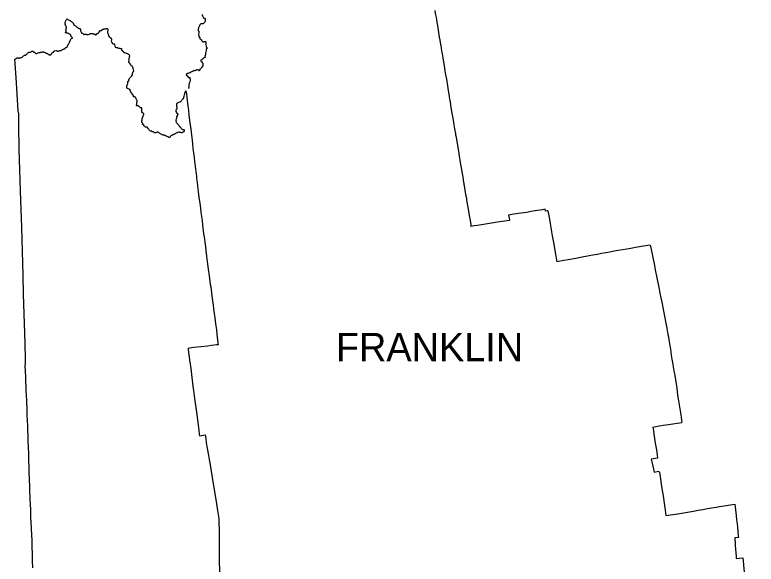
# Model space of a CAD drawing. Extents: x 1104458 to 2179854, y 15641624 to 17244911.
# Drawn here: x 1104458 to 1380839, y 16278003 to 16482866 of the extents above; entities that cross this region are included whole.
import ezdxf

# ---------------------------------------------------------------- set-up
doc = ezdxf.new("R2010")
doc.units = 0
doc.layers.add('ANNOTATION', color=7, linetype='Continuous')
doc.layers.add('CO BORDER', color=7, linetype='Continuous')

msp = doc.modelspace()

# ---------------------------------------------------------------- linework, layer by layer
at = {"layer": 'CO BORDER'}
for points in [[(1261052, 16484417), (1261224, 16483380), (1261498, 16481910), (1261631, 16481149), (1261802, 16480030), (1261997, 16478885), (1262714, 16474568), (1262900, 16473357), (1263165, 16471854), (1263235, 16471402), (1263424, 16470391)], [(1105767, 16446280), (1105725, 16447090), (1104983, 16459446), (1104458, 16466379), (1104525, 16466379), (1104625, 16466346), (1104708, 16466398), (1104775, 16466454), (1104833, 16466530), (1104983, 16466631), (1105258, 16466779), (1105457, 16466854), (1105658, 16466812), (1105791, 16466723), (1105933, 16466664), (1106049, 16466648), (1106149, 16466697), (1106257, 16466789), (1106308, 16466805), (1106416, 16466822), (1106658, 16466904), (1106958, 16466995), (1107132, 16467130), (1107616, 16467471), (1107732, 16467573), (1107907, 16467753), (1108016, 16467812), (1108116, 16467789), (1108324, 16467812), (1108507, 16467871), (1108599, 16467921), (1108782, 16468121), (1108916, 16468331), (1109057, 16468429), (1109174, 16468472), (1109232, 16468597), (1109316, 16468738), (1109507, 16468862), (1109682, 16468915), (1109899, 16468948), (1110240, 16468889), (1110357, 16468905), (1110591, 16469079), (1110690, 16469164), (1110849, 16469279), (1111032, 16469295), (1111132, 16469295), (1111282, 16469230), (1111374, 16469164), (1111457, 16469030), (1111582, 16468997), (1111741, 16468931), (1111907, 16468780), (1112132, 16468531), (1112307, 16468455), (1112440, 16468406), (1112565, 16468413), (1112715, 16468429), (1112932, 16468515), (1113174, 16468639), (1113498, 16468764), (1113915, 16468807), (1114174, 16468931), (1114548, 16468931), (1114690, 16469013), (1114965, 16469003), (1115157, 16468931), (1115415, 16468931), (1115540, 16468915), (1115707, 16468823), (1115757, 16468754), (1115882, 16468646), (1116056, 16468597), (1116298, 16468554), (1116448, 16468537), (1116557, 16468462), (1116707, 16468331), (1116790, 16468163), (1116957, 16468062), (1117132, 16468022), (1117248, 16468013), (1117390, 16467953), (1117440, 16467873), (1117748, 16467922), (1117915, 16467965), (1118007, 16468047), (1118123, 16468241), (1118190, 16468431), (1118257, 16468533), (1118431, 16468697), (1118565, 16468756), (1118706, 16468831), (1119015, 16469172), (1119231, 16469382), (1119373, 16469481), (1119840, 16469566), (1119981, 16469530), (1120273, 16469356), (1120423, 16469281), (1120631, 16469290), (1120748, 16469340), (1120981, 16469497), (1121114, 16469550), (1121415, 16469573), (1121564, 16469550), (1121748, 16469582), (1121914, 16469691), (1122123, 16469858), (1122189, 16469940), (1122489, 16470075), (1122681, 16470130), (1122789, 16470098), (1122881, 16470114), (1123123, 16470340), (1123348, 16470573), (1123506, 16470655), (1123698, 16470741), (1123881, 16470849), (1124047, 16470908), (1124156, 16470997), (1124131, 16471115), (1124147, 16471239), (1124147, 16471341), (1124181, 16471456), (1124306, 16471689), (1124464, 16472014), (1124564, 16472191), (1124681, 16472338), (1124781, 16472555), (1124864, 16472699), (1125131, 16473339), (1125347, 16473831), (1125447, 16473949), (1125630, 16474064), (1125889, 16474149), (1125930, 16474182), (1125939, 16474281), (1125930, 16474340), (1125764, 16474474), (1125672, 16474530), (1125589, 16474622), (1125522, 16474724), (1125447, 16474907), (1125389, 16475032), (1125297, 16475314), (1125222, 16475416), (1125147, 16475472), (1125047, 16475564), (1124880, 16475688), (1124664, 16475813), (1124456, 16475957), (1124181, 16476049), (1123814, 16476082), (1123681, 16476088), (1123531, 16476141), (1123431, 16476207), (1123397, 16476249), (1123389, 16476321), (1123406, 16476407), (1123472, 16476531), (1123589, 16476623), (1123605, 16476672), (1123622, 16476774), (1123572, 16477040), (1123547, 16477197), (1123531, 16477365), (1123505, 16477499), (1123564, 16477696), (1123622, 16477755), (1123681, 16477922), (1123689, 16478014), (1123664, 16478113), (1123664, 16478221), (1123681, 16478296), (1123647, 16478398), (1123597, 16478480), (1123547, 16478621), (1123489, 16478707), (1123389, 16478923), (1123272, 16479248), (1123289, 16479399), (1123289, 16479573), (1123256, 16479648), (1123247, 16479789), (1123230, 16479907), (1123230, 16479980), (1123272, 16480173), (1123339, 16480373), (1123464, 16480606), (1123564, 16480823), (1123780, 16481164), (1123814, 16481266), (1123897, 16481315), (1124105, 16481223), (1124272, 16481121), (1124430, 16480997), (1124522, 16480947), (1124672, 16480882), (1124922, 16480757), (1125072, 16480688), (1125197, 16480613), (1125347, 16480531), (1125497, 16480406), (1125605, 16480340), (1125980, 16479973), (1126089, 16479881), (1126147, 16479838), (1126255, 16479730), (1126289, 16479688), (1126322, 16479632), (1126314, 16479579), (1126347, 16479422), (1126405, 16479264), (1126447, 16479199), (1126488, 16479146), (1126630, 16479022), (1126680, 16478999)], [(1174314, 16483037), (1174349, 16482778), (1174395, 16482617), (1174456, 16482430), (1174585, 16482270), (1174830, 16481787), (1174960, 16481643), (1175092, 16481613), (1175250, 16481594), (1175349, 16481541), (1175430, 16481463), (1175461, 16481387), (1175475, 16481269), (1175383, 16480964), (1175397, 16480879), (1175360, 16480731), (1175364, 16480573), (1175360, 16480406), (1175271, 16480216), (1175158, 16480029), (1174902, 16479809), (1174748, 16479665), (1174604, 16479566), (1174370, 16479550), (1174144, 16479514), (1173952, 16479501), (1173817, 16479455), (1173647, 16479337), (1173577, 16479205), (1173406, 16479058), (1173337, 16478976), (1173273, 16478746), (1173193, 16478566), (1173010, 16478287), (1172939, 16478113), (1172877, 16477982), (1172769, 16477352), (1172795, 16477083), (1172866, 16476938), (1172963, 16476853), (1173027, 16476735), (1173046, 16476499), (1173021, 16476216), (1172959, 16475777), (1172954, 16475577), (1172996, 16475301), (1173058, 16475098), (1173070, 16474930), (1173097, 16474697), (1173143, 16474563), (1173259, 16474517), (1173382, 16474481), (1173456, 16474412), (1173487, 16474336), (1173499, 16474169), (1173461, 16473995), (1173450, 16473897), (1173583, 16473867), (1173878, 16473707), (1173990, 16473523), (1174044, 16473362), (1174172, 16473182), (1174267, 16472988), (1174398, 16472903), (1174580, 16472847), (1174880, 16472853), (1175064, 16472873), (1175331, 16472893), (1175474, 16472939), (1175581, 16472870), (1175611, 16472775), (1175669, 16472742), (1175692, 16472666), (1175648, 16472283), (1175608, 16472060), (1175595, 16471859), (1175624, 16471692), (1175801, 16471177), (1175812, 16470960), (1175909, 16470842), (1176127, 16470593), (1176123, 16470426), (1176068, 16470268), (1176033, 16470186), (1175950, 16470189), (1175899, 16470150), (1175836, 16470002), (1175795, 16469701), (1175625, 16468966), (1175602, 16468723), (1175587, 16468500), (1175554, 16468198), (1175568, 16468100), (1175548, 16467958), (1175477, 16467817), (1175434, 16467778), (1175379, 16467588), (1175342, 16467430), (1175369, 16467220), (1175391, 16467102), (1175389, 16467020), (1175328, 16466928), (1175161, 16466909), (1175035, 16466879), (1174731, 16466744), (1174628, 16466640), (1174575, 16466508), (1174538, 16466384), (1174478, 16466302), (1174351, 16466233), (1174232, 16466160), (1174140, 16466121), (1173918, 16465944), (1173815, 16465846), (1173739, 16465796), (1173761, 16465688), (1173956, 16465501), (1174013, 16465432), (1174344, 16465071), (1174433, 16464953), (1174495, 16464786), (1174509, 16464674), (1174539, 16464258), (1174542, 16464074), (1174511, 16463851), (1174449, 16463683), (1174403, 16463536), (1174384, 16463454), (1174315, 16463362), (1174180, 16463293), (1174052, 16463188), (1173991, 16463096), (1173972, 16462998), (1173562, 16462624), (1173402, 16462588), (1173382, 16462479), (1173361, 16462305), (1173358, 16462181), (1173339, 16462089), (1173287, 16462023), (1173227, 16461977), (1173135, 16461971), (1173013, 16462066), (1172950, 16462184), (1172860, 16462253), (1172786, 16462296), (1172703, 16462325), (1172654, 16462368), (1172538, 16462371), (1172328, 16462309), (1172176, 16462230), (1171990, 16462151), (1171713, 16462069), (1171645, 16462020), (1171552, 16461981), (1171461, 16462007), (1171404, 16462053), (1171312, 16462036), (1171230, 16462066), (1171113, 16462076), (1171020, 16462013), (1170934, 16461899), (1170823, 16461810), (1170636, 16461682), (1170460, 16461626), (1170334, 16461607), (1170099, 16461538), (1169938, 16461443), (1169894, 16461344), (1169808, 16461246), (1169640, 16461200), (1169303, 16461069), (1169110, 16461032), (1168992, 16460993), (1168859, 16460970), (1168502, 16460740), (1168434, 16460665), (1168391, 16460642), (1168355, 16460544), (1168620, 16460176), (1168798, 16459989), (1168944, 16459819), (1169228, 16459553), (1169411, 16459523), (1169561, 16459533), (1169669, 16459507), (1169758, 16459405), (1169752, 16459185), (1169801, 16458851), (1169819, 16458592), (1169798, 16458434), (1169708, 16457886), (1169645, 16457696), (1169566, 16457574), (1169469, 16457351), (1169430, 16457145), (1169373, 16456905), (1169332, 16456288), (1169291, 16456039), (1169284, 16455763), (1169247, 16455622), (1169234, 16455475), (1169208, 16455425)], [(1126680, 16478999), (1126858, 16478871), (1127016, 16478713), (1127205, 16478621), (1127302, 16478467), (1127432, 16478362), (1127526, 16478316), (1127703, 16478201), (1127851, 16478129), (1127960, 16478047), (1128012, 16477972), (1128096, 16477877), (1128260, 16477762), (1128372, 16477732), (1128720, 16477712), (1128815, 16477657), (1128910, 16477571), (1128954, 16477437), (1128973, 16477319), (1128973, 16477086), (1128981, 16476882), (1129070, 16476613), (1129171, 16476449), (1129259, 16476357), (1129351, 16476154), (1129497, 16476075), (1129791, 16475941), (1129936, 16475826), (1130031, 16475682), (1130059, 16475508), (1130158, 16475478), (1130273, 16475459), (1130390, 16475481), (1130568, 16475609), (1130802, 16475662), (1130894, 16475675), (1131010, 16475668), (1131206, 16475557), (1131405, 16475560), (1131612, 16475537), (1131887, 16475544), (1132138, 16475596), (1132248, 16475642), (1132350, 16475734), (1132443, 16475790), (1132553, 16475878), (1132621, 16475908), (1133128, 16475911), (1133294, 16475908), (1133443, 16475852), (1133548, 16475767), (1133764, 16475728), (1133914, 16475731), (1134072, 16475728), (1134188, 16475698), (1134348, 16475495), (1134430, 16475442), (1134578, 16475386), (1134754, 16475416), (1134841, 16475531), (1134918, 16475619), (1134956, 16475787), (1134990, 16475833), (1135041, 16475856), (1135125, 16475872), (1135232, 16475842), (1135366, 16475856), (1135468, 16475954), (1135536, 16476000), (1135648, 16476115), (1135760, 16476262), (1135830, 16476394), (1135967, 16476548), (1135994, 16476623), (1136212, 16476958), (1136431, 16477043), (1136530, 16477040), (1136597, 16477030), (1136689, 16477043), (1136962, 16477296), (1137080, 16477358), (1137174, 16477424), (1137292, 16477496), (1137375, 16477476), (1137593, 16477519), (1137745, 16477598), (1137956, 16477686), (1138305, 16477660), (1138476, 16477821), (1138609, 16477824), (1138792, 16477821), (1138883, 16477785), (1138988, 16477673), (1139060, 16477571), (1139100, 16477502), (1139131, 16477417), (1139155, 16477368), (1139162, 16477325), (1139161, 16477286), (1139174, 16477151), (1139090, 16476836), (1139052, 16476636), (1139040, 16476512), (1139020, 16476371), (1139032, 16476213), (1139093, 16476020), (1139173, 16475882), (1139226, 16475688), (1139289, 16475564), (1139369, 16475426), (1139423, 16475291), (1139454, 16475183), (1139419, 16475134), (1139400, 16475058), (1139374, 16474993), (1139463, 16474917), (1139578, 16474845), (1139657, 16474710), (1139671, 16474602), (1139738, 16474583), (1139950, 16474435), (1140073, 16474356), (1140131, 16474346), (1140188, 16474313), (1140263, 16474294), (1140367, 16474149), (1140430, 16474005), (1140462, 16473962), (1140501, 16473844), (1140512, 16473644), (1140519, 16473595), (1140516, 16473493), (1140506, 16473434), (1140513, 16473395), (1140435, 16473287), (1140450, 16473228), (1140448, 16473136), (1140436, 16473021), (1140482, 16472837), (1140538, 16472758), (1140576, 16472624), (1140623, 16472516), (1140679, 16472447), (1140710, 16472371), (1140759, 16472319), (1140882, 16472224), (1141153, 16472099), (1141352, 16472053), (1141442, 16472017), (1141509, 16471997), (1141582, 16471938), (1141635, 16471728), (1141738, 16471233), (1141839, 16470980), (1141854, 16470914), (1141911, 16470836), (1142025, 16470767), (1142199, 16470737), (1142290, 16470701), (1142697, 16470639), (1142919, 16470540), (1143126, 16470485), (1143300, 16470449), (1143624, 16470406), (1143831, 16470350), (1144022, 16470360), (1144172, 16470347), (1144221, 16470314), (1144260, 16470212), (1144279, 16469996), (1144368, 16469582), (1144457, 16469481), (1144563, 16469386), (1144719, 16469323), (1144859, 16469254), (1144938, 16469100), (1144984, 16468959), (1145072, 16468821), (1145387, 16468756), (1145676, 16468647), (1145907, 16468582), (1146048, 16468529), (1146486, 16468392), (1146657, 16468254), (1146804, 16468149), (1146952, 16468060), (1147065, 16467932), (1147179, 16467830), (1147261, 16467801), (1147301, 16467719), (1147245, 16467519), (1147182, 16467355), (1147078, 16467197), (1147038, 16466958), (1146935, 16466512), (1146916, 16466436), (1146880, 16466344), (1146902, 16466210), (1146974, 16466092), (1146991, 16465826), (1146953, 16465626), (1146845, 16465337), (1146874, 16465202), (1147069, 16464996), (1147431, 16464520), (1147552, 16464376), (1147615, 16464238), (1147914, 16463890), (1148053, 16463795), (1148167, 16463690), (1148271, 16463529), (1148355, 16463267), (1148392, 16463076), (1148446, 16462916), (1148514, 16462673), (1148526, 16462479), (1148581, 16462361), (1148649, 16462135), (1148689, 16462043), (1148677, 16461908), (1148623, 16461767), (1148544, 16461646), (1148424, 16461498), (1148336, 16461324), (1148290, 16461167), (1148252, 16460977), (1148215, 16460544), (1148220, 16460419), (1148209, 16460321), (1148166, 16460288), (1148090, 16460258), (1148024, 16460268), (1147981, 16460209), (1147927, 16460088), (1147897, 16459904), (1147854, 16459828), (1147565, 16459612), (1147486, 16459481), (1147305, 16459271), (1147175, 16459074), (1147096, 16458933), (1146943, 16458811), (1146889, 16458680), (1146841, 16458431), (1146877, 16458214), (1146840, 16458090), (1146781, 16458050), (1146688, 16458017), (1146579, 16457988), (1146508, 16457850), (1146484, 16457565), (1146440, 16457184), (1146410, 16456994), (1146357, 16456869), (1146266, 16456597), (1146238, 16456462), (1146211, 16456397), (1146201, 16456347), (1146141, 16456292), (1146099, 16456269), (1146047, 16456210), (1146035, 16456052), (1146038, 16455868), (1146074, 16455658), (1146206, 16455590), (1146378, 16455517), (1146535, 16455429), (1146625, 16455370), (1146979, 16455252), (1147144, 16455170), (1147277, 16455143), (1147324, 16455042), (1147335, 16454825), (1147305, 16454641), (1147344, 16454556), (1147591, 16454441), (1147630, 16454349), (1147642, 16454172), (1147710, 16453920), (1147841, 16453824), (1147980, 16453739), (1148028, 16453660), (1148087, 16453385), (1148207, 16453214), (1148355, 16453145), (1148504, 16453089), (1148567, 16452945), (1148589, 16452830), (1148591, 16452604), (1148628, 16452437), (1148748, 16452250)], [(1263424, 16470391), (1263554, 16469400), (1263717, 16468354), (1263983, 16466877), (1264272, 16465171), (1264514, 16463810), (1264826, 16461982), (1265067, 16460430), (1265357, 16458833), (1265910, 16455535), (1266390, 16452396), (1266570, 16451352), (1266665, 16450883), (1266719, 16450522)], [(1168263, 16454497), (1168149, 16454438), (1168020, 16454280), (1167951, 16454175), (1167931, 16454077), (1167920, 16453949), (1167926, 16453877), (1167807, 16453811), (1167772, 16453739), (1167734, 16453572), (1167686, 16453322), (1167656, 16453132), (1167609, 16452968), (1167488, 16452479), (1167457, 16452269), (1167361, 16452115), (1167279, 16451833), (1167234, 16451702), (1167181, 16451593), (1167086, 16451462), (1167025, 16451383), (1166923, 16451292), (1166863, 16451246), (1166741, 16451049), (1166628, 16450885), (1166439, 16450671), (1166250, 16450478), (1166115, 16450383), (1165938, 16450311), (1165609, 16450196), (1165246, 16449996), (1165060, 16449904), (1164882, 16449809), (1164797, 16449743), (1164736, 16449635), (1164714, 16449444), (1164761, 16449034), (1164779, 16448785), (1164836, 16448408), (1164865, 16448247), (1164876, 16448040), (1164830, 16447906), (1164828, 16447814), (1164751, 16447725), (1164672, 16447578), (1164602, 16447463), (1164538, 16447266), (1164496, 16446948), (1164541, 16446757), (1164716, 16446442), (1164781, 16446367), (1165097, 16446065), (1165196, 16446003), (1165252, 16445934), (1165276, 16445885), (1165241, 16445819), (1165177, 16445622), (1165116, 16445514), (1165035, 16445307), (1164999, 16445199), (1164757, 16444858), (1164729, 16444756), (1164717, 16444641), (1164739, 16444523), (1164770, 16444448), (1164776, 16444356), (1164731, 16444208), (1164633, 16444018), (1164505, 16443588), (1164546, 16443227), (1164539, 16442994), (1164585, 16442817), (1164718, 16442532), (1164865, 16442410), (1164995, 16442289), (1165077, 16442246), (1165393, 16441905), (1165499, 16441810), (1165604, 16441705), (1165636, 16441656), (1165787, 16441383), (1165882, 16441190), (1166022, 16441127), (1166146, 16441081), (1166244, 16441013), (1166257, 16440888), (1166385, 16440701), (1166522, 16440488), (1166634, 16440350), (1166790, 16440238), (1167053, 16440114), (1167243, 16440051), (1167410, 16440071), (1167551, 16440035), (1167565, 16439950), (1167544, 16439776), (1167541, 16439658), (1167347, 16439280), (1167210, 16439142), (1167091, 16439064), (1166863, 16438952), (1166671, 16438916), (1166553, 16438903), (1166338, 16438926), (1166181, 16438988), (1165973, 16439018), (1165782, 16439057), (1165599, 16439064), (1165450, 16439083), (1165097, 16438985), (1164937, 16438906), (1164835, 16438834), (1164386, 16438572), (1164192, 16438476), (1163802, 16438227), (1163668, 16438198), (1163516, 16438135), (1163406, 16438079), (1163256, 16438093), (1163112, 16438014), (1162968, 16437902), (1162882, 16437810), (1162746, 16437725), (1162535, 16437620), (1162467, 16437574), (1162354, 16437400), (1162318, 16437295), (1162233, 16437230), (1162089, 16437167), (1161948, 16437171), (1161816, 16437217), (1161685, 16437285), (1161569, 16437322), (1161511, 16437351), (1161272, 16437440), (1161082, 16437502), (1160959, 16437574), (1160895, 16437659), (1160747, 16437738), (1160541, 16437820), (1160335, 16437925), (1160212, 16437978), (1160028, 16437984), (1159913, 16438020), (1159680, 16438033), (1159483, 16438138), (1159278, 16438263), (1159013, 16438345), (1158776, 16438519), (1158547, 16438667), (1158358, 16438772), (1158169, 16438887), (1157907, 16439060), (1157775, 16439087), (1157458, 16439090), (1157357, 16439024), (1157230, 16438962), (1157003, 16438877), (1156901, 16438847), (1156801, 16438841), (1156634, 16438811), (1156528, 16438890), (1156333, 16439077), (1156251, 16439123), (1156235, 16439139), (1156103, 16439211), (1155987, 16439238), (1155695, 16439211), (1155533, 16439369), (1155501, 16439451), (1155445, 16439503), (1155352, 16439480), (1155226, 16439434), (1155052, 16439464), (1154915, 16439635), (1154695, 16439825), (1154567, 16440018), (1154388, 16440176), (1154332, 16440278), (1154153, 16440406), (1154105, 16440491), (1154076, 16440668), (1154053, 16440750), (1153972, 16440829), (1153842, 16440924), (1153700, 16440944), (1153610, 16440996), (1153443, 16440993), (1153284, 16440973), (1153184, 16440976), (1153087, 16441062), (1152924, 16441183), (1152631, 16441475), (1152373, 16441790), (1152244, 16441934), (1152170, 16441954), (1152112, 16441997), (1152089, 16442066), (1152142, 16442164), (1152177, 16442256), (1152149, 16442430), (1152082, 16442433), (1151984, 16442476), (1151902, 16442522), (1151813, 16442650), (1151763, 16442942), (1151816, 16443050), (1151811, 16443198), (1151825, 16443381), (1151892, 16443729), (1151926, 16444038), (1151983, 16444293), (1152036, 16444418), (1152115, 16444549), (1152185, 16444697), (1152196, 16444782), (1152223, 16444854), (1152233, 16444930), (1152252, 16445005), (1152296, 16445094), (1152316, 16445196), (1152352, 16445317), (1152414, 16445458), (1152528, 16445665), (1152590, 16445803), (1152591, 16445855), (1152545, 16445973), (1152488, 16446049), (1152457, 16446108), (1152416, 16446144), (1152351, 16446186), (1152292, 16446170), (1152177, 16446249), (1152086, 16446285), (1151997, 16446364), (1151856, 16446682), (1151835, 16446849), (1151798, 16447010), (1151780, 16447286), (1151801, 16447427), (1151797, 16447578), (1151825, 16447692), (1151867, 16448027), (1151755, 16448171), (1151546, 16448185), (1151323, 16448224), (1151192, 16448329), (1151087, 16448457), (1150982, 16448568), (1150777, 16448683), (1150646, 16448778), (1150547, 16448837), (1150423, 16448867), (1150274, 16448913), (1150041, 16448910), (1149926, 16448965), (1149853, 16449041), (1149781, 16449136), (1149809, 16449257), (1149853, 16449343), (1149915, 16449490), (1149944, 16449638), (1149956, 16449772), (1149951, 16449871), (1149960, 16449930), (1149949, 16450114), (1149910, 16450206), (1149972, 16450347), (1150065, 16450429), (1150102, 16450543), (1150113, 16450635), (1150149, 16450727), (1150100, 16450793), (1150046, 16450944), (1149837, 16451219), (1149672, 16451613), (1149530, 16451885), (1149524, 16451977), (1149485, 16452086), (1149461, 16452128), (1149421, 16452164), (1149123, 16452246), (1148847, 16452230), (1148748, 16452250)], [(1168263, 16454497), (1168411, 16453552), (1168584, 16452010), (1168965, 16448828), (1169172, 16447302), (1169369, 16445580), (1169757, 16442417), (1169950, 16441049), (1170179, 16439221), (1170297, 16437942), (1170388, 16437082), (1170518, 16436058), (1170679, 16434871), (1170881, 16432886), (1171039, 16431416), (1171285, 16429654), (1171451, 16428119), (1171811, 16425379), (1172031, 16423486), (1172138, 16422686)], [(1266719, 16450522), (1266912, 16449229), (1267434, 16446047), (1267637, 16444902), (1268021, 16442799), (1268185, 16441854), (1268418, 16440401), (1268536, 16439731), (1268715, 16438613), (1268800, 16438120), (1268871, 16437753)], [(1105767, 16446280), (1105800, 16441772), (1105967, 16432740), (1106167, 16425108), (1106450, 16417090), (1106533, 16413740)], [(1268871, 16437753), (1269098, 16436483), (1269595, 16433343), (1269831, 16432067), (1270158, 16430135), (1270399, 16428616), (1270664, 16427031), (1270899, 16425784), (1271217, 16423704), (1271468, 16422379), (1271772, 16420505), (1271989, 16419088), (1272278, 16417418), (1272535, 16415889), (1272674, 16414961), (1272792, 16414318), (1272854, 16413927)], [(1172138, 16422686), (1172228, 16421793), (1172403, 16420307), (1172579, 16419004), (1172815, 16417026), (1172975, 16415783), (1173188, 16413972), (1173381, 16412643), (1173634, 16410773), (1173840, 16409145), (1174247, 16406124), (1174428, 16404454), (1174857, 16401222), (1175027, 16400028), (1175287, 16398066), (1175526, 16396379), (1175718, 16394936), (1175952, 16392807), (1176066, 16391914), (1176221, 16390838), (1176302, 16389919), (1176554, 16387974)], [(1106533, 16413740), (1106884, 16403691), (1107434, 16385735), (1107628, 16378756)], [(1272854, 16413927), (1273010, 16413032), (1273204, 16411778), (1273337, 16411076), (1273843, 16407972), (1274406, 16404737), (1274499, 16404104), (1274505, 16403963)], [(1303208, 16409800), (1302862, 16409754), (1302280, 16409659), (1302140, 16410358), (1301225, 16410187), (1298489, 16409734), (1296912, 16409495), (1295218, 16409209), (1292257, 16408750), (1290530, 16408488), (1289086, 16408238), (1288536, 16408153), (1288747, 16406991), (1288847, 16406293), (1288880, 16406191), (1288062, 16406060), (1285117, 16405620), (1279986, 16404823), (1278401, 16404590), (1276858, 16404344), (1275656, 16404140), (1274505, 16403963)], [(1303208, 16409800), (1303422, 16408586), (1303733, 16406631), (1304031, 16405020), (1304289, 16403533), (1304553, 16401881), (1304812, 16400484), (1305124, 16398624), (1305351, 16397387), (1305632, 16395717), (1306124, 16392885), (1306349, 16391432), (1306491, 16390730)], [(1341340, 16397022), (1338795, 16396586), (1337301, 16396297), (1335832, 16396038), (1334072, 16395759), (1332569, 16395494), (1331059, 16395238), (1329391, 16394965), (1327938, 16394683), (1326236, 16394378), (1324817, 16394102), (1323190, 16393814), (1321704, 16393525), (1319919, 16393210), (1318516, 16392938), (1315287, 16392357), (1313651, 16392045), (1310705, 16391514), (1309119, 16391205), (1306491, 16390730)], [(1341340, 16397022), (1341467, 16396573), (1342427, 16391694), (1342759, 16390097), (1343057, 16388518), (1343332, 16387108), (1343687, 16385359), (1344639, 16380529), (1344955, 16379010), (1345261, 16377363), (1345608, 16375700), (1346496, 16371064), (1347151, 16367832), (1347481, 16366067), (1347694, 16365034), (1347882, 16363971), (1347961, 16363653)], [(1176554, 16387974), (1176876, 16385579), (1177062, 16384358), (1177339, 16382354), (1177478, 16381419), (1177769, 16379165), (1178175, 16376136), (1178384, 16374749), (1178574, 16373154), (1178797, 16371527), (1178971, 16370008), (1179197, 16368597), (1179402, 16366901), (1179602, 16365408), (1179799, 16363771), (1179920, 16362668), (1180187, 16360567), (1180312, 16359832)], [(1107628, 16378756), (1108150, 16360360), (1108292, 16354350), (1108252, 16353155), (1108238, 16351633), (1108244, 16351364)], [(1347961, 16363653), (1348093, 16362803), (1348287, 16361625), (1348512, 16360181), (1348848, 16358226), (1349020, 16357183), (1349206, 16355920), (1349448, 16354479), (1349753, 16352609), (1349917, 16351582), (1350026, 16350821), (1350179, 16350103), (1350475, 16348397), (1350733, 16346789), (1350981, 16345135), (1351201, 16343744), (1351400, 16342150), (1351694, 16340299), (1351905, 16338862), (1352139, 16337363), (1352694, 16333659), (1352841, 16332747), (1352954, 16331802), (1353086, 16330886)], [(1180312, 16359832), (1179662, 16359765), (1177827, 16359529), (1176358, 16359361), (1171254, 16358764), (1169654, 16358557), (1169071, 16358489)], [(1169071, 16358489), (1169131, 16357964), (1169252, 16357137), (1169385, 16355828), (1169564, 16354489), (1169626, 16353695), (1169671, 16353446), (1170028, 16351021), (1170449, 16347668), (1170872, 16344427), (1171103, 16342730), (1171473, 16339788), (1172173, 16334696), (1172781, 16329965), (1173047, 16327975), (1173225, 16326538), (1173329, 16325918)], [(1108244, 16351364), (1108280, 16350701), (1108442, 16347099), (1108476, 16346193), (1108495, 16345360), (1108535, 16345065), (1108567, 16343654), (1108617, 16342716), (1108696, 16340747), (1108749, 16339235), (1108800, 16338316), (1108887, 16335875), (1108958, 16334162), (1108987, 16333336), (1109060, 16331892), (1109151, 16329326), (1109201, 16327715), (1109283, 16326062), (1109318, 16325183), (1109365, 16323706), (1109431, 16322069), (1109449, 16321183), (1109500, 16319799), (1109575, 16317945), (1109588, 16317151), (1109605, 16316951)], [(1342314, 16329134), (1342525, 16327884), (1342737, 16326497), (1342976, 16324817), (1343240, 16323117), (1343619, 16320585), (1343880, 16318777), (1344079, 16317530), (1342499, 16317248), (1341679, 16317107), (1342007, 16315683), (1342275, 16314577), (1342525, 16313390), (1342767, 16312267), (1343898, 16312566), (1344518, 16312743), (1344691, 16312445), (1344808, 16312267), (1345058, 16310716), (1345204, 16309754), (1345480, 16307848), (1345729, 16306267), (1345932, 16304826), (1346111, 16303465), (1346652, 16299935), (1346867, 16298297), (1347042, 16297100), (1347196, 16296119)], [(1342314, 16329134), (1343400, 16329302), (1344829, 16329538), (1346225, 16329784), (1348164, 16330083), (1349802, 16330348), (1351431, 16330604), (1353086, 16330886)], [(1173329, 16325918), (1175392, 16326206), (1175503, 16325557), (1175618, 16324704)], [(1175618, 16324704), (1175847, 16323280), (1176179, 16321272), (1177231, 16315091), (1178003, 16310264), (1178286, 16308673), (1179388, 16302082), (1180027, 16298033), (1180395, 16295789), (1180520, 16294995), (1180541, 16294779)], [(1109605, 16316951), (1109687, 16313896), (1109723, 16313043), (1109824, 16308916), (1109880, 16307466), (1109919, 16305770), (1109926, 16304812), (1110009, 16303188), (1110072, 16301685), (1110124, 16300832), (1110251, 16297636), (1110340, 16295238), (1110427, 16293726), (1110457, 16292948), (1110503, 16292147), (1110575, 16290668), (1110612, 16289608), (1110671, 16288712), (1110738, 16287075), (1110811, 16284729), (1110874, 16281599), (1110909, 16279103), (1110986, 16276606)], [(1347196, 16296119), (1349828, 16296529), (1352369, 16296959), (1355972, 16297556), (1357501, 16297815), (1359232, 16298110), (1360963, 16298439), (1362642, 16298711), (1364131, 16298996), (1365953, 16299315), (1367223, 16299515), (1368870, 16299787), (1370349, 16300020), (1372839, 16300427)], [(1372839, 16300427), (1372979, 16299446), (1373096, 16298294), (1373326, 16296214), (1373532, 16294492), (1373692, 16293028), (1373815, 16291775), (1374171, 16288524), (1374209, 16287989), (1372823, 16287838), (1373010, 16285673), (1373029, 16284957)], [(1180541, 16294779), (1180628, 16289457), (1180647, 16287600), (1180673, 16286081), (1180661, 16284306), (1180634, 16281839), (1180681, 16279752), (1180697, 16278112), (1180747, 16276560), (1180746, 16273374), (1180762, 16271356), (1180846, 16263886), (1180880, 16260028), (1180918, 16257459), (1180925, 16256215), (1180969, 16255523)], [(1373029, 16284957), (1373358, 16280906), (1373410, 16280171), (1375854, 16280344), (1375971, 16279222), (1376114, 16277703), (1376289, 16276148), (1376447, 16274587), (1376660, 16272841), (1376765, 16271919), (1377894, 16272113), (1380026, 16272490), (1380451, 16269780), (1380717, 16268166), (1380839, 16267237)]]:
    msp.add_lwpolyline(points, dxfattribs=at)

# ---------------------------------------------------------------- texts
at = {"layer": 'ANNOTATION'}
msp.add_text('FRANKLIN', height=10560.2, dxfattribs=at).set_placement((1224144, 16353705))

doc.saveas('drawing.dxf')
